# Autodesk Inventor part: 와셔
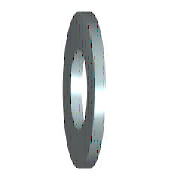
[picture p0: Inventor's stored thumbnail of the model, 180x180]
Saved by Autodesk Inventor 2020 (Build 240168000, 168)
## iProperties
IsCustomPart: 1
Created: 2012-02
Part Number: 와셔
Material: 강철, 연강
Description: 평면 와셔
Document SubType Name: Modeling
Standard: KS B 1326
Designer: mduedu
Standards Organization: KS
Language: ko-KR
Size Designation: 8x15.5
Categories: <MemberInstance><Categories><Category DisplayName="조임쇠" InternalName="e4da775c-781d-43d5-af7c-5136215cf5a6" Mnemonic="FSTN"><Category DisplayName="와셔" InternalN
Density: 7.85 g/cm^3
Appearance: 주황색
Mass: 1.67392 g
Surface Area: 3.86683 cm^2
Volume: 0.213239 cm^3
Author: mduedu
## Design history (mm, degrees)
sketch "스케치"
  geometry: C1 r 7.75 at (0, 0); C2 r 4.2 at (0, 0); 1 further point
  constraints: 2 centre point, 2 coincident
  dimensions: "d0" = 8.4 diameter of C2 (= SD1); "d1" = 15.5 diameter of C1 (= SD2)
extrude "본체" new body sketch "스케치" distance "d2" = 1.6 (= SD); taper "d3" = 0 deg
workaxis "Work Axis1"
workplane "Work Plane1"
body "Solid1"
other parameters: "SD1" = 8.4 [user parameter; used in 1 equation term], "SD2" = 15.5 [user parameter; used in 1 equation term], "SD" = 1.6 [user parameter; used in 1 equation term], "d4" = 0, "d5" = 0, "d6" = 0, "d7" = 0, "NND" = 8 [user parameter]
